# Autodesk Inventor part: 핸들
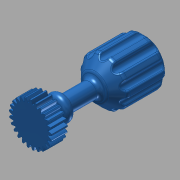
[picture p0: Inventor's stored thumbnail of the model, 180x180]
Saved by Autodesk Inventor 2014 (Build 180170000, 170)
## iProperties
Created: 2017-04
Part Number: 핸들
Material: 강철, 연강
Document SubType Name: Modeling
Designer: mduedu
Categories: <?xml version="1.0" encoding="UTF-16"?> <MemberInstance><Categories><FamilyTemplate><FamilyTemplateParameter ValueType="xs:double" Id="1" ObjectReferenceKey="da
Density: 7.86 g/cm^3
Appearance: 청록색
Mass: 209.32 g
Surface Area: 78.6033 cm^2
Volume: 26.631 cm^3
CustomPartVersion: 1
Author: mduedu
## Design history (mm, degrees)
sketch "Sketch1"
  geometry: C1 r 13.5 at (0, 0)
  constraints: 1 centre point
  dimensions: "d0" = 27 diameter of C1 (= da_da)
extrude "Extrusion1" new body sketch "Sketch1" distance "d1" = 10 (= da_b); taper "d2" = 0 deg
workplane "Work Plane2"
sketch "Sketch2"
  geometry: C1 r 13.5 at (0, 0) reference; C2 r 12.5 at (0, 0)
  constraints: 1 centre point, 1 coincident
  dimensions: "d3" = 25 diameter of C2 (= da_dw)
feature "피치 지름" sketch "Sketch2" dims "d4" = 10, "d5" = 0
workplane "Work Plane8"
workplane "Work Plane9"
feature "스퍼 기어" dims "da_b" = 10, "da_d" = 25, "da_aw" = 25, "da_da" = 27, "da_df" = 22.5, "da_dw" = 25, angle "da_beta" = 0 deg, "da_lefttooth" = 0, "da_righttooth" = 0
sketch "스케치3"
  geometry: C1 r 5 at (0, 0); 1 further point
  constraints: 1 centre point, 1 coincident
  dimensions: "d49" = 10 diameter of C1
extrude "돌출2" join sketch "스케치3" distance "d50" = 60; taper "d51" = 0 deg
sketch "스케치4"
  geometry: C1 r 15 at (0, 0); 1 further point
  constraints: 1 centre point, 1 coincident
  dimensions: "d52" = 30 diameter of C1
extrude "돌출3" join sketch "스케치4" distance "d53" = 30; taper "d54" = 0 deg
chamfer "모따기1" distance "d55" = 7; stored, may be unused: second distance "d56" = 2, angle "d57" = 45 deg
sketch "스케치5"
  geometry: L1 (0, 2.2)-(0, -13.2) reference; L2 (0, -5)-(8, -5); L3 (8, -5)-(8, -11); L4 (8, -11)-(0, -11); L5 (0, -11)-(0, -5); 1 further point
  constraints: 8 end point, 2 parallel, 1 horizontal, 1 perpendicular, 1 point on line
  dimensions: "d58" = 5 distance from line of L2 point (0, 0); "d59" = 6 distance of L2.end L3.end; "d60" = 16 diameter of L3 L1
revolve "회전1" sketch "스케치5" stored, may be unused: angle "d61" = 90 deg
fillet "모깎기1" dims "d62" = 3
fillet "모깎기2" dims "d65" = 3
sketch "스케치9"
  geometry: L1 (15, -60)-(-15, -60) reference; L2 (0, -60)-(0, 0); L3 (0, -66.771)-(0, -60); A1 r 20 centre (0, -46.771) between (0, -66.771) and (15, -60)
  constraints: 4 end point, 2 point on circle, 1 centre point, 1 collinear, 1 line through centre, 1 midpoint, 1 perpendicular
  dimensions: "d84" = 20 radius of A1
revolve "회전4" sketch "스케치9" stored, may be unused: angle "d86" = 90 deg
fillet "모깎기3" dims "d72" = 3
sketch "스케치6"
  geometry: C1 r 2.5 at (0, 15); 2 further points
  constraints: 2 vertical alignment, 1 centre point, 1 other
  dimensions: "d66" = 5 diameter of C1
extrude "돌출4" cut sketch "스케치6" stored distance "d67" = 60; taper "d68" = 0 deg
fillet "모깎기4" dims "d73" = 1
node "작업 평면12"
sketch "스케치10"
  geometry: C1 r 6 at (0, 0); 1 further point
  constraints: 1 centre point, 1 coincident
  dimensions: "d87" = 12 diameter of C1
extrude "돌출5" cut sketch "스케치10" distance "d88" = 5; taper "d89" = 0 deg
fillet "모깎기5" dims "d90" = 1
body "Solid1"
pattern_circular "원형 패턴2" dims angle "d75" = 360 deg
body "Srf1"
other parameters: "d16" = 25 (= da_aw), "d17" = 0, "d34" = 1.25664 (computed from da_z), "d39" = 0, "d41" = 0, "d43" = 25 (= da_aw), "d46" = 25 (= da_aw), "d47" = 0, "d48" = 0
